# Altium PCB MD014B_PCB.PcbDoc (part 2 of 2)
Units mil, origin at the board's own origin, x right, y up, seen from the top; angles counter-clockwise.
Board outline 2500 x 1545 mil, 2 copper layers (Top Layer, Bottom Layer), stack 64.8 mil thick; 63 components, 34 nets, 144 pads, 182 vias.
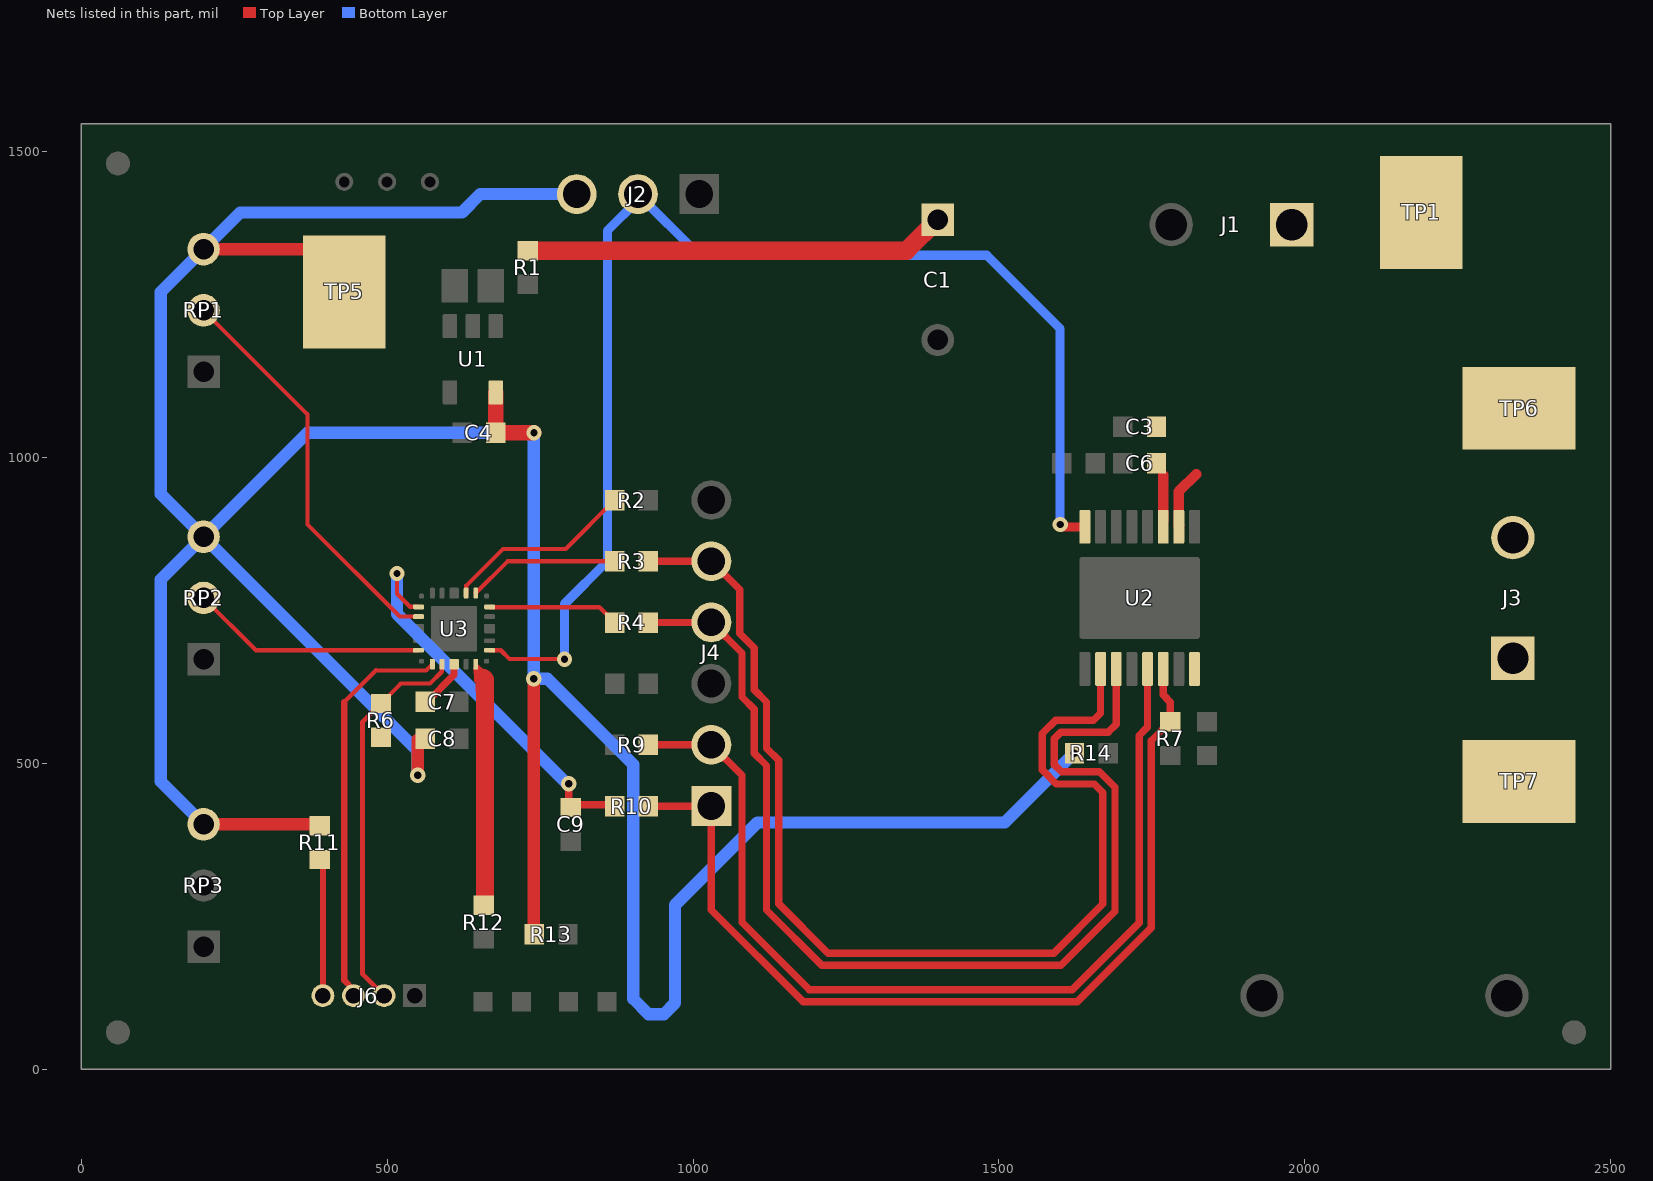
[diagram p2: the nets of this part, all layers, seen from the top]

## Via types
v1: diameter 25, hole 12, Top Layer to Bottom Layer, tented both sides, 165 vias
v2: diameter 19.68, hole 7.87, Top Layer to Bottom Layer, tented both sides, 12 vias
v3: diameter 19.68, hole 7.87, Top Layer to Bottom Layer, 3 vias
v4: diameter 25/25 (per signal layer), hole 12, Top Layer to Bottom Layer, tented both sides, 1 vias
v5: diameter 25, hole 12, Top Layer to Bottom Layer, 1 vias

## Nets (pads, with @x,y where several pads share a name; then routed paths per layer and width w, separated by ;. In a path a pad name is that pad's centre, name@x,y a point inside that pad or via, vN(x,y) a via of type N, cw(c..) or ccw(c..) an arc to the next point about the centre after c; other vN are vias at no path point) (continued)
nSLEEP: J4.4 R4.1 U2.3 | length 1827.7
  Top Layer w12: R4.1@927.01,729.78 J4.4@1029.78,729.78 ; J4.4@1030,730 1080,680 1080,608.11 1099.87,588.23 1099.87,516.34 1120,496.21 1120,260 1210.38,169.62 1601.52,169.62 1689.54,257.65 1689.54,460.46 1664.27,485.73 1602.11,485.73 1590.46,497.38 1590.46,540.09 1600.82,550.45 1678.34,550.45 1691.61,563.73 U2.3@1691.61,653.86 U2.3@1691.61,667.09
nSLEEP_MCU: R4.2 U3.11 | length 214.3
  Top Layer w7: U3.11@667.95,754.78 846.89,754.78 R4.2@871.89,729.78
OUT1: J3.1 TP7.1 U2.8
OUT2: J3.2 TP6.1 U2.10 | length 101.7
  Top Layer w12: U2.10@1793.98,886.14 U2.10@1796.83,889
  Top Layer w17: U2.10@1793.98,886.14 1793.98,943.98 1822.17,972.17
PH_IN2: J4.5 R3.1 U2.2 | length 1845.9
  Top Layer w12: R3.1@927.01,829.78 J4.5@1029.78,829.78 ; J4.5@1030,830 1076.35,783.65 1076.35,711.75 1099.87,688.23 1099.87,620.13 1120,600 1120,524.32 1139.87,504.44 1139.87,470.13 1140,470 1140,270 1220.5,189.5 1589.5,189.5 1669.67,269.67 1669.67,451.86 1655.67,465.86 1593.88,465.86 1570.59,489.15 1570.59,548.32 1592.59,570.32 1654.59,570.32 1666.02,581.76 U2.2@1666.02,653.86 ; U2.2@1663.17,661 U2.2@1666.02,663.86
PMODE: J2.2 U2.16 U3.7 | length 2094
  Top Layer w6: v1(1600,890) v1@1603.86,886.14
  Top Layer w7: U3.7@667.52,684.35 685.65,684.35 700,670 v1(790,670)
  Top Layer w12: U2.16@1640.43,896.14 U2.16@1640.43,898.27
  Top Layer w15: v1@1603.86,886.14 U2.16@1640.43,886.14
  Bottom Layer w15: v1(790,670) 790,760 860,830 860,1370.1 J2.2@910,1420.1 ; J2.2@902.5,1427.6 J2.2@910,1420.1 ; v1(1600,890) 1600,1210 1480,1330 1010,1330 J2.2@910,1430 J2.2@910,1420.1
PWM1: R2.2 U3.14 | length 312.7
  Top Layer w7: U3.14@629.13,777.85 629.57,778.29 629.57,790.27 689.3,850 792.11,850 R2.2@871.89,929.78
PWM2: R3.2 U3.13 | length 248.4
  Top Layer w7: U3.13@644.88,778.02 696.64,829.78 R3.2@871.89,829.78
SBWTCK: J6.3 U3.1 | length 656.1
  Top Layer w7: 430,600 481.82,651.82 482.32,651.32 563.79,651.32 U3.1@574.01,661.54
  Top Layer w10: 430,600 430,145 445,130 J6.3@445,120
SBWTDIO: J6.2 R6.2 U3.2 | length 637.8
  Top Layer w7: R6.2@490,597.56 522.44,630 570.03,630 589.32,649.29 589.32,661.27 U3.2@589.76,661.71
  Top Layer w8: R6.2@490,597.56 460,567.56 460,155 J6.2@495,120
SPD_REF_1: RP1.2 U3.20 | length 664.1
  Top Layer w7: RP1.2@200,1240 370,1070 370,890 520.53,739.47 U3.20@551.38,739.47
SPD_REF_2: RP2.2 U3.23 | length 386.9
  Top Layer w7: RP2.2@200,770 285.65,684.35 U3.23@551.38,684.35
STATUS: R12.2 U3.5 | length 430.1
  Top Layer w6: U3.5@643.94,656.66 644.01,656.6 U3.5@644.01,654.53 ; 644.87,635.13 644.87,646.16 644.01,647.03 U3.5@644.01,654.53 ; U3.5@644.88,661.71 659.32,647.27 651.27,647.27 U3.5@644.01,654.53
  Top Layer w30: 656.87,639.17 659.32,636.72 659.32,620.68 ; R12.2@660,270.13 660,620
V_IPROPI: J4.1 R7.2 R10.1 U2.6 | length 1554.5
  Top Layer w12: R10.1@927.01,429.78 J4.1@1029.78,429.78 ; J4.1@1030,430 1030,260 1180,110 1628.11,110 1749.16,231.06 1749.16,536.95 ; 1749.39,536.95 R7.2@1780,567.56 1780,599.45 1774.1,605.35 1774.1,605.9 1768.39,611.61 U2.6@1768.39,663.86
V_IPROPI_MCU: C9.1 R10.2 U3.19 | length 649.9
  Top Layer w7: v1(516.13,810) 516.13,776.93 537.51,755.56 U3.19@551.03,755.56
  Top Layer w12: C9.1@796.96,430.6 v1(796.96,466.52) ; C9.1@799.45,432.22 869.45,432.22 R10.2@871.89,429.78
  Bottom Layer w6: v1@790.22,469.78 v1@800.22,469.78
  Bottom Layer w20: v1(516.13,810) 516.13,743.87 v1@790.22,469.78
VCC: C4.1 C7.1 C8.1 J2.3 R6.1 R11.1 R13.2 R14.1 RP1.3 RP2.3 RP3.3 TP5.1 U1.5 U3.3 | length 5954.3
  Top Layer w12: C7.1@562.44,600 565.28,600 609.45,644.17 U3.3@609.45,661.71
  Top Layer w20: RP3.3@200,400 R11.1@387.44,400 ; RP1.3@200,1340 430,1340 TP5.1@445,1325 ; v4@550,490 C8.1@550,538.5 ; v1(739.63,637.74) 739.63,220.87 R13.2@740,220.49
  Top Layer w25: C4.1@677.4,1047.87 U1.5@677.4,1105.87 ; C4.1@677.56,1040 v1(740,1040)
  Bottom Layer w20: RP3.3@200,400 130,470 130,800 RP2.3@200,870 ; 370,1040 RP2.3@200,870 ; 370.37,1040 v1(740,1040) 739.63,1040 v1(739.63,637.74) 762.28,637.74 902.13,497.89 902.13,114.92 927.42,89.63 952.58,89.63 970.69,107.74 970.69,268.18 1105.31,402.8 1509.57,402.8 v1(1623.11,516.34) ; v4@550,490 550,520 RP2.3@200,870 ; J2.3@810,1430 652.25,1430 622.25,1400 260,1400 RP1.3@200,1340 130,1270 130,940 RP2.3@200,870
  other v4: 550,480
VCCX: J6.4 R11.2 | length 232.4
  Top Layer w10: J6.4@395,120 R11.2@395,352.44
VM: C1.1 C3.1 C6.1 J1.1 R1.1 TP1.1 U2.11 | length 776.9
  Top Layer w12: U2.11@1767.56,896.97 1768.39,896.14 U2.11@1768.39,886.14
  Top Layer w17: U2.11@1768.39,896.14 1768.39,970.83
  Top Layer w30: R1.1@730,1337.56 1349.13,1337.56 C1.1@1400,1388.43
VREF: J4.2 R9.1 U2.5 | length 1584
  Top Layer w12: R9.1@927.01,529.78 J4.2@1029.78,529.78 ; J4.2@1030,530 1080,480 1080,240 1190,130 ; 1190,129.87 1619.87,129.87 1729.29,239.29 1729.29,545.18 1740.93,556.83 1741.16,556.83 1742.8,558.46 U2.5@1742.8,663.86
pads on no net: FID1.1 FID2.1 FID3.1 H1.0 H2.0 H3.0 H4.0 LBL1.0 SH-J1.0 U1.2 U2.17@1730,770 U3. U3.6 U3.9 U3.10 U3.12 U3.18 U3.21 U3.22 U3.24

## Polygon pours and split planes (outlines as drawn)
GND on Top Layer "TOP_LAYER_GND_P038" (solid, remove dead copper, pour order 38): 0,1545 2500,1545 2500,0 0,0
VCC on Top Layer "TOP_LAYER_VCC_P034" (solid, remove dead copper, pour order 34): 569.27,510.73 580,531.3 580,618.7 611.3,650 620,650 620,670 586.22,670 486.22,570 471.3,570 471.3,524.72 469.33,522.76 469.33,510.73
NetC2_1 on Top Layer "TOP_LAYER_NETC2_1_P032" (solid, remove dead copper, pour order 32): 696.1,1308.52 640,1308.52 640,1255.02 660,1235.02 660,1194.46 690.56,1194.46 749.61,1261.69 749.61,1300
OUT1 on Top Layer "TOP_LAYER_OUT1_P026" (solid, remove dead copper, pour order 26): 1810,680 2200,680 2227,707 2227,790 2500,790 2500,400 2060,400 1940,520 1840,620 1810,620
OUT2 on Top Layer "TOP_LAYER_OUT2_P024" (solid, remove dead copper, pour order 24): 2497.48,770 2497.48,1157.5 1980.63,1157.5 1787.48,964.35 1787.48,953.25 1787.48,857.5 1797.48,857.5 1797.48,917.5 2197.48,917.5 2224.48,890.5 2224.48,777.5 2489.98,777.5
VM on Top Layer "TOP_LAYER_VM_P022" (solid, remove dead copper, pour order 22): 1560,1300 1070,1300 1070,1545 1900,1545 1900,1431.15 1690,1431.15 1690,1300 1633.14,1300 1610,1300
VM on Top Layer "TOP_LAYER_VM_P020" (solid, remove dead copper, pour order 20): 1730,1070.67 1900,1240.67 1900,1545 2300,1545 2300,1180 2000,1180 1760.65,940.65 1730,971.3
GND on Bottom Layer "BOTTOM_LAYER_GND_P030" (solid, remove dead copper, pour order 30): 0,1545 2500,1545 2500,0 0,0

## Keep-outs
Keep-Out Layer:
  text ".Layer_Name" at 577,-858.49 h60

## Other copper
Top Layer:
  text ".Layer_Name" at 577,-858.49 h60
Bottom Layer:
  text ".Layer_Name" at 577,-858.49 h60

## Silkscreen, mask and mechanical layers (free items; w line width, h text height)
Top Overlay:
  rectangle: 2222.09,210.13 2410.82,270.25
  lines w10: 1570,480 1880,480 1880,640.85 1880,942.55 1880,1083.39 1570,1083.39 1570,480
  text "37 Vdc" at 2310,1510 h60 r270
  text "4.5 Vdc -" at 2360,1510 h60 r270
  text "VM" at 2410,1510 h60 r270
  text "EN/IN1 PWM" at 300,1470 h60 r270
  text "3.3 V" at 520,1380 h60 r270
  text "3.3 V" at 790,1360 h60 r270
  text "PMODE" at 890,1360 h60 r270
  text "GND" at 990,1360 h60 r270
  text "OUT2" at 2190,1160 h60 r270
  text "GND" at 1730,1130 h60
  text "VM" at 1950,1130 h60
  text "PH/IN2 PWM" at 300,1000 h60 r270
  text "3.3 A RMS/OUTx" at 1990,980 h60 r270
  text "Board rated for" at 2050,950 h60 r270
  text "EN/IN1" at 1090,910 h60
  text "PH/IN2" at 1090,810 h60
  text "nSLEEP" at 1090,710 h60
  text "nFAULT" at 1090,610 h60
  text "OUT1" at 2190,540 h60 r270
  text "VREF" at 1090,500 h60
  text "VREF" at 300,450 h60 r270
  text "DRV8874x" at 1570,430 h60
  text "IPROPI" at 1090,410 h60
  text "'.PRJ_Number'.PCB_Rev-" at 2189,288 h72.83
  text "Status" at 620,150 h60
  text "Fault" at 780,150 h60
  text "GND" at 1860,40 h60
  text ".Layer_Name" at 577,-858.49 h60
Bottom Overlay:
  text ".Layer_Name" at 577,-858.49 h60
Top Paste:
  text ".Layer_Name" at 577,-858.49 h60
Bottom Paste:
  text ".Layer_Name" at 577,-858.49 h60
Top Solder:
  text ".Layer_Name" at 577,-858.49 h60
  text ".Layer_Name" at 577,-858.49 h60
Bottom Solder:
  text ".Layer_Name" at 577,-858.49 h60
Drill Guide:
  text ".Layer_Name" at 577,-858.49 h60
M1 Board Outline:
  the board outline again, w10
  text ".Layer_Name" at 577,-858.49 h60
M2 Board Dimensions:
  rectangle: 0,-275 125,-150
  rectangle: 125,-400 500,-275
  lines w7: 0,-275 1000,-275 ; 125,-400 125,-150 ; 250,-400 250,-150 ; 500,-400 500,-150 ; 750,-400 750,-150 ; 0,-400 1000,-400 1000,-150 0,-150 0,-400
  text ".Layer_Name" at 577,-858.49 h60
M3 3D STEP Top:
  text ".Layer_Name" at 577,-858.49 h60
M4 3D STEP Bottom:
  text ".Layer_Name" at 577,-858.49 h60
M5 Assembly Top:
  lines w10: -292,-930.17 6308,-930.17 ; -292,-726.83 6310,-726.83 ; -292,-523.5 -292,-1133.5 3713,-1133.5 6310,-1133.5 6310,-523.5 -291.5,-523.5 -291.5,-1133.5 1284,-1133.5 ; 2173,-1133.5 2173,-523.5 ; 3440,-726.83 3440,-523.5 ; 4280,-726.83 4280,-523.5 ; 4902,-1140 4902,-937.17
  text "COMPONENTS MARKED 'DNP' SHOULD NOT BE POPULATED." at 1153.5,-318.5 h60
  text "ASSEMBLY VARIANT:" at 1153,-434 h60
  text ".VariantName" at 2189,-434 h60
  text "PCB VIEWED FROM TOP SIDE" at -228.5,-655.67 h60
  text "BOARD #:" at 2248,-655.67 h60
  text ".PRJ_Number" at 2793.5,-655.67 h60
  text "REV:" at 3638,-655.67 h60
  text ".PCB_Rev" at 3929.5,-655.67 h60
  text "SVN REV:" at 4476,-655.67 h60
  text ".VersionControl_RevNumber" at 4982,-655.67 h60
  text "TID #:" at 2248,-859 h60
  text ".TID" at 2793.5,-859 h60
  text "PLOT NAME =" at -228.5,-1064.34 h60
  text ".plot_File_Name" at 577,-1064.34 h60
  text "GENERATED    :" at 2250,-1064.34 h60
  text ".Print_Date" at 3119.5,-1064.34 h60
  text ".Print_Time" at 3848.5,-1064.34 h60
  text "TEXAS INSTRUMENTS" at 5113,-1064.34 h60
M6 Assembly Bottom:
  lines w10: -292.5,-727.33 6309.5,-727.33 ; -290.5,-930.67 6309.5,-930.67 ; 1115.5,-1140.5 1115.5,-937.67 ; 1737.5,-727.33 1737.5,-524 ; 2577.5,-727.33 2577.5,-524 ; 3844.5,-1134 3844.5,-524 ; 4733.5,-1134 6309,-1134 6309,-524 -292.5,-524 -292.5,-1134 2304.5,-1134 6309.5,-1134 6309.5,-524
  text "COMPONENTS MARKED 'DNP' SHOULD NOT BE POPULATED." at 6102,-318 h60
  text ".VariantName" at 5058,-434 h60
  text "ASSEMBLY VARIANT:" at 6097,-434 h60
  text ".VersionControl_RevNumber" at 1035.5,-656.17 h60
  text "SVN REV:" at 1541.5,-656.17 h60
  text ".PCB_Rev" at 2088,-656.17 h60
  text "REV:" at 2379.5,-656.17 h60
  text ".PRJ_Number" at 3224,-656.17 h60
  text "BOARD #:" at 3769.5,-656.17 h60
  text "PCB VIEWED FROM BOTTOM SIDE" at 6246,-656.17 h60
  text ".TID" at 3224,-859.5 h60
  text "TID #:" at 3769.5,-859.5 h60
  text "TEXAS INSTRUMENTS" at 904.5,-1064.84 h60
  text ".Print_Time" at 2169,-1064.84 h60
  text ".Print_Date" at 2898,-1064.84 h60
  text "GENERATED    :" at 3767.5,-1064.84 h60
  text ".plot_File_Name" at 5440.5,-1064.84 h60
  text "PLOT NAME =" at 6246,-1064.84 h60
M9 Title Sheet:
  drawing of 57 lines, arcs and shapes, not listed
  text "1" at 739.84,8036.5 h60
  text "2" at 3235.5,8036.5 h60
  text "3" at 5724.84,8036.5 h60
  text "4" at 8231.51,8036.5 h60
  text "5" at 10730.5,8036.5 h60
  text "6" at 13235.5,8036.5 h60
  text "A" at -416.5,6893.5 h60
  text "A" at 14383.5,6893.5 h60
  text "B" at 14383.5,4513.5 h60
  text "B" at -436.5,4318 h60
  text "C" at -416.5,2138.5 h60
  text "C" at 14383.5,2138.5 h60
  text "PROJECT TITLE:" at 11343.5,277.5 h60
  text ".PRJ_Title" at 11393.5,144.17 h60
  text "DESIGNED FOR:" at 11343.5,-23.5 h60
  text ".PRJ_Customer" at 11393.5,-163.5 h60
  text "D" at -416.5,-231.5 h60
  text "D" at 14383.5,-231.5 h60
  text "FILE NAME:" at 11343.5,-323.5 h60
  text ".PCB_File_Name_No_Path" at 11393.5,-443.5 h60
  text "Texas Instruments (TI) and/or its licensors do not warrant the accuracy or completeness of this specification" at 6374,-605.34 h60
  text "ENGINEER:" at 11343.5,-613.5 h60
  text "LAYOUT BY:" at 12848.5,-613.5 h60
  text "or any information contained therein. TI and/or its licensors do not warrant that this design will meet" at 6329.01,-718 h60
  text ".PRJ_Engineer" at 11393.5,-768.49 h60
  text ".PCB_Layout" at 12899,-768.49 h60
  text "the specifications, will be suitable for your application or fit for any particular purpose, or will operate in" at 6329.01,-830.67 h60
  text ".Layer_Name" at 577,-858.49 h60
  text "ALTIUM DESIGNER VERSION:" at 12848.5,-923.5 h60
  text "an implementation. TI and/or its licensors do not warrant that the design is production worthy. You should" at 6329.01,-943.33 h60
  text "completely validate and test your design implementation to confirm the system functionality for your application." at 6374,-1056 h60
  text ".print_Scale" at 11393.5,-1056.83 h60
  text ".Application_BuildNumber" at 12899,-1056.83 h60
  text "1" at 739.84,-1263.5 h60
  text "2" at 3235.5,-1263.5 h60
  text "3" at 5724.84,-1263.5 h60
  text "4" at 8231.51,-1263.5 h60
  text "5" at 10730.5,-1263.5 h60
  text "6" at 13235.5,-1263.5 h60
M10 Fab Notes:
  drawing of 189 lines, arcs and shapes, not listed
  text "DESIGN INFORMATION" at 12382.02,6356.17 h60
  text "MIN. TRACK WIDTH:" at 11737.46,6224.05 h60
  text "6" at 12833.7,6224.05 h60
  text "MIL" at 12988.46,6224.05 h60
  text "MIN. CLEARANCE:" at 11737.46,6099.92 h60
  text "0.2" at 12773.7,6099.93 h60
  text "mm" at 12988.46,6099.92 h60
  text "MIN. VIA PAD SIZE:" at 11737.46,5975.8 h60
  text "24" at 12803.71,5975.8 h60
  text "MIL" at 12988.46,5975.8 h60
  text "0.05mm (2MIL)" at 12432.46,5845.9 h60
  text "MINIMUM ANNULAR RING" at 11408.23,5837.67 h60
  text "EXTERNAL" at 13140.46,5837.67 h60
  text "PER" at 11608.23,5727.55 h60
  text "IPC-D-275 CLASS 2 LEVEL C" at 11828.23,5727.54 h60
  text "MIL, HOLES" at 13316.46,5627.07 h60
  text "+/-" at 12924,5618.48 h60
  text "+/-" at 13778,5618.48 h60
  text "REGISTRATION TOLERANCES:" at 11408.23,5617.42 h60
  text "METAL" at 12608,5617.42 h60
  text "5" at 13184.2,5617.42 h60
  text "3" at 14017.2,5617.42 h60
  text "MIL" at 14133.46,5617.42 h60
  text "HOLE SIZE TOLERANCE (UNLESS OTHERWISE SPECIFIED):" at 11408.23,5519.1 h60
  text "+/-" at 13778,5516.23 h60
  text "3" at 14017.2,5515.17 h60
  text "MIL" at 14133.46,5515.17 h60
  text "MATERIAL:" at 11333.46,5377.52 h60
  text "FR-4 High Tg" at 12319.9,5249 h60
  text "FR-408" at 11754.46,5236.49 h60
  text "OTHER" at 13242.46,5236.49 h60
  text "X" at 12170,5230 h60
  text "62 MIL (1.6mm) +/-10%" at 12074.56,5093.46 h60
  text "X" at 11954.46,5091.01 h60
  text "THICKNESS:" at 11408.23,5085.24 h60
  text "OTHER" at 13359.46,5085.24 h60
  text "TOLERANCE:" at 11408.23,4946.92 h60
  text "X" at 12256.46,4946.92 h60
  text "ANSI IPC-6012 TYPE 3 CLASS 2" at 12434.48,4946.92 h60
  text "OTHER +/-" at 12434.46,4802.73 h60
  text "BOW & TWIST:" at 11408.23,4657.54 h60
  text "X" at 12256.46,4657.54 h60
  text "ANSI IPC-6012 TYPE 3 CLASS 2" at 12434.48,4657.54 h60
  text "OTHER +/-" at 12434.46,4510.85 h60
  text "DRILLING:" at 11333.46,4380.23 h60
  text "NC_DRILL FILES" at 13094.46,4275.04 h60
  text "REFERENCE:" at 11408.23,4271.1 h60
  text "X" at 12065.46,4271.01 h60
  text "AS SHOWN" at 12243.46,4271.1 h60
  text "X" at 12966.46,4271.1 h60
  text "OTHER" at 13392.46,4128.85 h60
  text "PTH COPPER THICKNESS:" at 11407.91,4125.32 h60
  text "X" at 12547.14,4125.32 h60
  text "20-30 um" at 12675.14,4125.32 h60
  text "BOARD FINISH:" at 11333.46,3977.73 h60
  text "SILKSCREEN:" at 11488.68,3867.6 h60
  text "X" at 12446.46,3867.6 h60
  text "TOP" at 12563.46,3867.6 h60
  text "X" at 12956.46,3867.6 h60
  text "BOTTOM" at 13074.46,3867.6 h60
  text "SILKSCREEN COLOR:" at 11488.68,3712.41 h60
  text "X" at 12445.46,3712.41 h60
  text "WHITE" at 12563.46,3712.41 h60
  text "OTHER" at 13074.46,3712.41 h60
  text "X" at 12576.46,3568.96 h60
  text "GREEN" at 12694.46,3568.96 h60
  text "OTHER" at 13312.46,3568.96 h60
  text "SOLDER RESIST COLOR:" at 11488.68,3562.1 h60
  text "X" at 12576.46,3414.71 h60
  text "MATTE" at 12694.46,3414.71 h60
  text "SEMI-GLOSS" at 13312,3414.07 h60
  text "IMMERSION GOLD (ENIG)" at 12394.46,3241.94 h60
  text "ENEPIG" at 13732,3234.72 h60
  text "SURFACE FINISH:" at 11333.46,3233.72 h60
  text "X" at 12216.46,3233.72 h60
  text "IMM. TIN/SILVER OR EQUIV" at 11663,3096.4 h60
  text "OTHER" at 13094.46,3092.47 h60
  text "ARRAY/PANEL:" at 11333.46,2937.09 h60
  text "CUT AND TRIM PER M1 BOARD OUTLINE" at 12394.46,2928.87 h60
  text "N.C. ROUTE" at 12394.46,2792.9 h60
  text "X" at 13082.46,2792.9 h60
  text "V. SCORE" at 13260.46,2792.9 h60
  text "CERTIFICATION:" at 11333.46,2663.77 h60
  text "MATERIALS AND WORKMANSHIP FOR ALL PCBS" at 12058.46,2663.77 h60
  text "TO MEET OR EXCEED THE REQUIREMENTS OF:" at 12058.46,2569.71 h60
  text "X" at 11695.97,2441.08 h60
  text "ANSI IPC-A-600F CLASS ->" at 11823.96,2441.08 h60
  text "X" at 13471.97,2441.08 h60
  text "2" at 13581.96,2441.08 h60
  text "1" at 13266.96,2439.58 h60
  text "3" at 13935.96,2439.58 h60
  text "X" at 12507.97,2293.39 h60
  text "RoHS" at 12635.96,2293.39 h60
  text "OTHER" at 13280.36,2293.39 h60
  text "PER ORDER" at 13677.42,2293.39 h60
  text "ALL BOARDS MUST MEET OR EXCEED UL94-V0 REQUIREMENTS." at 11350,2170 h60
  text "PCB MUST BEAR THE UL94V-0 UL REGISTERED MATERIAL ID NUMBER" at 11350,2070 h60
  text "ALL BOARDS MUST MEET THE UL MOT 130 C HEAT RATING" at 11351,1973.5 h60
  text "ADDITIONAL REQUIREMENTS:" at 11333.46,1854.08 h60
  text "MICROSECTION:" at 11408.23,1746.95 h60
  text "YES" at 12313.96,1746.95 h60
  text "REQUIRED" at 13175.46,1602.62 h60
  text "BARE BOARD ELEC. TEST:" at 11408.23,1599.76 h60
  text "NONE" at 12713.96,1599.76 h60
  text "X" at 13057.46,1599.76 h60
  text "PER ORDER" at 13767.46,1599.76 h60
  text "XX MIL VIAS REQUIRE NON-CONDUCTIVE FILL AND PLANARIZE" at 11576.38,1394.82 h60
  text "XX MIL VIAS REQUIRE CONDUCTIVE FILL AND PLANARIZE" at 11584.38,1290.84 h60
  text "OUTER XX MIL VIAS REQUIRE 50 OHM SINGLE-ENDED IMPEDANCE" at 11583.39,1127.46 h60
  text "LAYER 2 & 3 (INNER LAYERS) XX MIL WIDE, XX MIL SPACE / TRACES REQUIRE 100 OHM DIFFERENTIAL IMPEDANCE" at 11575.39,891.74 h60
  text ".Layer_Name" at 577,-858.49 h60
M11 Gerber Information:
  lines w10: -292,-930.17 6308,-930.17 ; -292,-726.83 6310,-726.83 ; -292,-523.5 -292,-1133.5 3713,-1133.5 6310,-1133.5 6310,-523.5 -291.5,-523.5 -291.5,-1133.5 1284,-1133.5 ; 2173,-1133.5 2173,-523.5 ; 3440,-726.83 3440,-523.5 ; 4280,-726.83 4280,-523.5 ; 4902,-1140 4902,-937.17
  text "ALL ARTWORK VIEWED FROM TOP SIDE" at -228.5,-655.67 h60
  text "BOARD #:" at 2248,-655.67 h60
  text ".PRJ_Number" at 2793.5,-655.67 h60
  text "REV:" at 3638,-655.67 h60
  text ".PCB_Rev" at 3929.5,-655.67 h60
  text "SVN REV:" at 4476,-655.67 h60
  text ".VersionControl_RevNumber" at 4982,-655.67 h60
  text "LAYER NAME =" at -228.5,-858.49 h60
  text "TID #:" at 2248,-859 h60
  text ".TID" at 2793.5,-859 h60
  text "PLOT NAME =" at -228.5,-1064.34 h60
  text ".plot_File_Name" at 577,-1064.34 h60
  text "GENERATED    :" at 2250,-1064.34 h60
  text ".Print_Date" at 3119.5,-1064.34 h60
  text ".Print_Time" at 3848.5,-1064.34 h60
  text "TEXAS INSTRUMENTS" at 5113,-1064.34 h60
M12 Stackup:
  drawing of 191 lines, arcs and shapes, not listed
  text "Layer" at 9797.84,7672.5 h60
  text "Name" at 10207.76,7672.5 h60
  text "Material" at 11137.5,7672.5 h60
  text "Thickness" at 11997.27,7672.5 h60
  text "Constant" at 12647.1,7672.5 h60
  text "Board Layer Stack" at 13216.96,7672.5 h60
  text "1" at 9797.84,7552.5 h60
  text "Top Overlay" at 10207.76,7552.5 h60
  text "2" at 9797.84,7432.5 h60
  text "Top Solder" at 10207.76,7432.5 h60
  text "Solder Resist" at 11137.5,7432.5 h60
  text "0.40mil" at 11997.27,7432.5 h60
  text "3.5" at 12647.1,7432.5 h60
  text "3" at 9797.84,7312.5 h60
  text "Top Layer" at 10207.76,7312.5 h60
  text "Copper" at 11137.5,7312.5 h60
  text "2.80mil" at 11997.27,7312.5 h60
  text "4" at 9797.84,7192.5 h60
  text "Dielectric1" at 10207.76,7192.5 h60
  text "FR-4" at 11137.5,7192.5 h60
  text "59.20mil" at 11997.27,7192.5 h60
  text "4.8" at 12647.1,7192.5 h60
  text "5" at 9797.84,7072.5 h60
  text "Bottom Layer" at 10207.76,7072.5 h60
  text "Copper" at 11137.5,7072.5 h60
  text "2.80mil" at 11997.27,7072.5 h60
  text "6" at 9797.84,6952.5 h60
  text "Bottom Solder" at 10207.76,6952.5 h60
  text "Solder Resist" at 11137.5,6952.5 h60
  text "0.40mil" at 11997.27,6952.5 h60
  text "3.5" at 12647.1,6952.5 h60
  text "7" at 9797.84,6832.5 h60
  text "Bottom Overlay" at 10207.76,6832.5 h60
  text ".Layer_Name" at 577,-858.49 h60
M13 Component Bodies Top:
  text ".Layer_Name" at 577,-858.49 h60
M14 Component Bodies Bottom:
  text ".Layer_Name" at 577,-858.49 h60
M15 Courtyards Top:
  text ".Layer_Name" at 577,-858.49 h60
M16 Courtyards Bottom:
  text ".Layer_Name" at 577,-858.49 h60
Drill Drawing:
  circle w10: c3083.72,1239.96 r16.58
  circle w10: c3083.72,1239.96 r27.63
  circle w10: c3083.72,867 r27.63
  lines w10: 3056.09,590.74 3083.72,604.55 3111.34,590.74 3097.53,618.36 3111.34,645.99 3083.72,632.18 3056.09,645.99 3069.9,618.36 3056.09,590.74 ; 3056.09,728.87 3069.9,728.87 3083.72,715.06 3097.53,728.87 3111.34,728.87 3097.53,742.68 3111.34,756.5 3097.53,756.5 3083.72,770.31 3069.9,756.5 3056.09,756.5 3069.9,742.68 3056.09,728.87 ; 3056.09,1018.95 3111.34,1018.95 3083.72,963.7 3056.09,1018.95 ; 3056.09,1101.83 3069.9,1101.83 3069.9,1088.02 3097.53,1088.02 3097.53,1101.83 3111.34,1101.83 3111.34,1129.46 3097.53,1129.46 3097.53,1143.27 3069.9,1143.27 3069.9,1129.46 3056.09,1129.46 3056.09,1101.83 ; 3056.09,1364.28 3083.72,1336.66 3111.34,1364.28 3083.72,1391.91 3056.09,1364.28
  lines w12: 3006,553.44 6237.49,553.44 ; 3006,1423.68 6237.49,1423.68 ; 3343.86,429.12 3343.86,1548 ; 3675.86,429.12 3675.86,1548 ; 4312.43,429.12 4312.43,1548 ; 4571.57,429.12 4571.57,1548 ; 4946.72,429.12 4946.72,1548 ; 5671.05,429.12 5671.05,1548 ; 3006,429.12 6237.49,429.12 6237.49,1548 3006,1548 3006,429.12
  text "Symbol" at 3080.59,1460.98 h72
  text "Quantity" at 3381.16,1460.98 h72
  text "Finished Hole Size" at 3713.16,1460.98 h72
  text "Plated" at 4349.72,1460.98 h72
  text "Hole Type" at 4608.86,1460.98 h72
  text "Drill Layer Pair" at 4984.02,1460.98 h72
  text "Hole Tolerance" at 5708.35,1460.98 h72
  text "15" at 3381.16,1336.66 h60
  text "7.87mil (0.200mm)" at 3713.16,1336.66 h60
  text "PTH" at 4349.72,1336.66 h60
  text "Round" at 4608.86,1336.66 h60
  text "Top Layer - Bottom Layer" at 4984.02,1336.66 h60
  text "167" at 3381.16,1212.34 h60
  text "12.00mil (0.305mm)" at 3713.16,1212.34 h60
  text "PTH" at 4349.72,1212.34 h60
  text "Round" at 4608.86,1212.34 h60
  text "Top Layer - Bottom Layer" at 4984.02,1212.34 h60
  text "3" at 3381.16,1088.02 h60
  text "17.72mil (0.450mm)" at 3713.16,1088.02 h60
  text "PTH" at 4349.72,1088.02 h60
  text "Round" at 4608.86,1088.02 h60
  text "Top Layer - Bottom Layer" at 4984.02,1088.02 h60
  text "4" at 3381.16,963.7 h60
  text "25.59mil (0.650mm)" at 3713.16,963.7 h60
  text "PTH" at 4349.72,963.7 h60
  text "Round" at 4608.86,963.7 h60
  text "Top Layer - Bottom Layer" at 4984.02,963.7 h60
  text "11" at 3381.16,839.38 h60
  text "33.47mil (0.850mm)" at 3713.16,839.38 h60
  text "PTH" at 4349.72,839.38 h60
  text "Round" at 4608.86,839.38 h60
  text "Top Layer - Bottom Layer" at 4984.02,839.38 h60
  text "9" at 3381.16,715.06 h60
  text "45.28mil (1.150mm)" at 3713.16,715.06 h60
  text "PTH" at 4349.72,715.06 h60
  text "Round" at 4608.86,715.06 h60
  text "Top Layer - Bottom Layer" at 4984.02,715.06 h60
  text "6" at 3381.16,590.74 h60
  text "51.18mil (1.300mm)" at 3713.16,590.74 h60
  text "PTH" at 4349.72,590.74 h60
  text "Round" at 4608.86,590.74 h60
  text "Top Layer - Bottom Layer" at 4984.02,590.74 h60
  text "215 Total" at 3381.16,466.42 h60
  text ".Layer_Name" at 577,-858.49 h60
M17 Embedded Cavity:
  text ".Layer_Name" at 577,-858.49 h60
M18 Embedded Assembly:
  text ".Layer_Name" at 577,-858.49 h60
M19 Embedded Keepout:
  text ".Layer_Name" at 577,-858.49 h60

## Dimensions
0,-400 to 1000,-400 on M2 Board Dimensions
0,0 to 0,1545 on M2 Board Dimensions
0,0 to 2500,0 on M2 Board Dimensions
